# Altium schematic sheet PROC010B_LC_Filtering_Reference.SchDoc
size 431 x 279 mm; Date: Not shown in title block; ApprovedBy: Not shown in title block; CheckedBy: Not shown in title block; Author: Not shown in title block; CompanyName: Not shown in title block; DrawnBy: Adrian Ozer; Engineer: Not shown in title block; Organization: Not shown in title block; Address1: Not shown in title block; Address2: Not shown in title block; Address3: Not shown in title block; Address4: Not shown in title block; DocumentNumber: 5; Revision: Use project parameter SCH_Rev; SheetNumber: 5; SheetTotal: 16; PageSetup: Record=PageOptions¦CenterHorizontal=True¦CenterVertical=True¦PrintScale=1.00¦XCorrection=1.00¦YCorrection=1.00¦PrintKind=0¦BorderSize=5000000¦LeftOffset=0¦BottomOffset=0¦Orientation=2¦PaperLength=1000¦PaperWidth=1000¦Scale=100¦PaperSource=15¦PrintQuality=600¦MediaType=1¦DitherType=10¦PaperKind=Letter¦PrintScaleMode=1
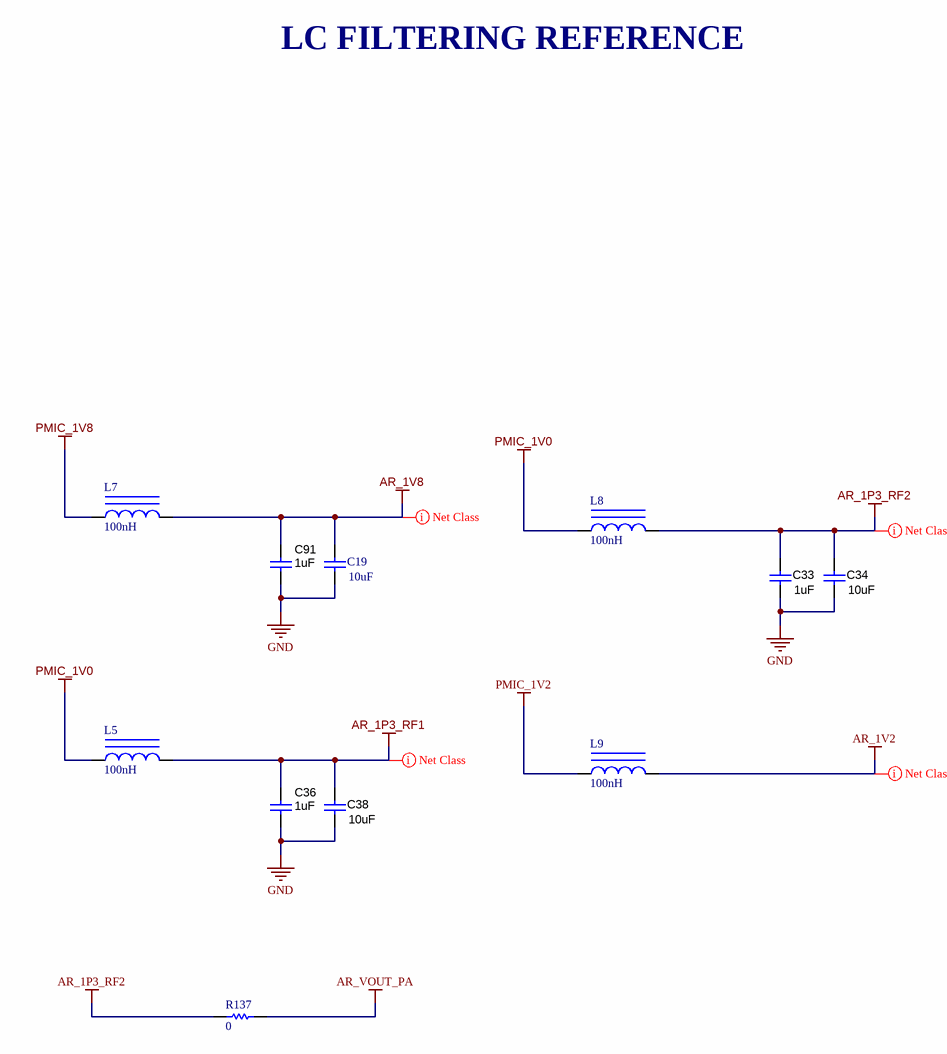
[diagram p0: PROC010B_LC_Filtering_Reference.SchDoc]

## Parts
C19  ValueDisplayed: 10uF  [0805_HV]  (hidden comment: GCM21BR71A106KE22L)
C33  ValueDisplayed: 1uF  [0603]  (hidden comment: GCM188R71C105KA64D)
C34  ValueDisplayed: 10uF  [0805_HV]  (hidden comment: GCM21BR71A106KE22L)
C36  ValueDisplayed: 1uF  [0603]  (hidden comment: GCM188R71C105KA64D)
C38  ValueDisplayed: 10uF  [0805_HV]  (hidden comment: GCM21BR71A106KE22L)
C91  ValueDisplayed: 1uF  [0603]  (hidden comment: GCM188R71C105KA64D)
L5  ValueDisplayed: 100nH  [NLCV32]  (hidden comment: NLCV32T-R10M-EFRD)
L7  ValueDisplayed: 100nH  [NLCV32]  (hidden comment: NLCV32T-R10M-EFRD)
L8  ValueDisplayed: 100nH  [NLCV32]  (hidden comment: NLCV32T-R10M-EFRD)
L9  ValueDisplayed: 100nH  [NLCV32]  (hidden comment: NLCV32T-R10M-EFRD)
R137  ValueDisplayed: 0  [0603]  (hidden comment: MCT06030Z0000ZP500)

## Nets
AR_1P3_RF1: C36.2 C38.2 L5.2
AR_1P3_RF2: C33.2 C34.2 L8.2 R137.1
AR_1V2: L9.2
AR_1V8: C19.1 C91.2 L7.2
AR_VOUT_PA: R137.2
GND: C19.2 C33.1 C34.1 C36.1 C38.1 C91.1
PMIC_1V0: L5.1 L8.1
PMIC_1V2: L9.1
PMIC_1V8: L7.1

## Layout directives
net class PWR: AR_1P3_RF1, AR_1P3_RF2, AR_1V2, AR_1V8

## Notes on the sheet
- LC FILTERING REFERENCE

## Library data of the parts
C19 = CMP-0008017-2: CAP, CERM, 10 uF, 10 V, +/- 10%, X7R, 0805; Manufacturer: MuRata; TaMin_C: -55°C; Polarized: N; SizeAreaWB_mm2: 6.75; Value1: Unknown; U/M: EA; Value: 10uF; TaMax_C: 125°C; SizeZ_mm: 1.45; SizeX_mm: 2; SizeY_mm: 1.25; Cap_Case: 0805; Value2: 10V; SizeArea_mm2: 2.5; Cap_F: 10µF; AEC Category: Q200
C33 C36 C91 = CMP-0007136-5: CAP, CERM, 1 uF, 16 V, +/- 10%, X7R, AEC-Q200 Grade 1, 0603; Manufacturer: MuRata; TaMin_C: -55°C; Polarized: N; SizeAreaWB_mm2: 4.68; Value1: Unknown; U/M: EA; Value: 1uF; TaMax_C: 125°C; SizeZ_mm: 1; SizeX_mm: 1.6; SizeY_mm: 0.8; Value2: 16V; SizeArea_mm2: 1.28; AEC Qualified: Y; Cap_F: 1µF; AEC Category: Q200
C34 C38 = CMP-0008017-2: CAP, CERM, 10 uF, 10 V, +/- 10%, X7R, 0805; Manufacturer: MuRata; TaMin_C: -55°C; Polarized: N; SizeAreaWB_mm2: 6.75; Value1: Unknown; U/M: EA; Value: 10uF; TaMax_C: 125°C; SizeZ_mm: 1.45; SizeX_mm: 2; SizeY_mm: 1.25; Cap_Case: 0805; Value2: 10V; SizeArea_mm2: 2.5; CompType: Capacitor; Cap_F: 10µF; AEC Category: Q200
L5 L7-L9 = CMP-0083745-1: Inductor, Wirewound, Ferrite, 100 nH, 2.85 A, 0.024 ohm, AEC-Q200 Grade 1, SMD; Manufacturer: TDK; Isat: 2.85A @ 10% inductance drop; Irms: 2.85A @ 40C rise; SizeAreaWB_mm2: 13.44; DCR_ohm: 0.024; Value: 100nH; Imax_A: 2.85A; SizeZ_mm: 2.5; SizeX_mm: 3.2; SizeY_mm: 2.2; SizeArea_mm2: 7.04; AEC Qualified: Y; AEC Grade: 1; AEC Category: Q200
R137 = CMP-0025884-3: RES, 0, 5%, 0.125 W, 0603; Manufacturer: Vishay/Beyschlag; Power_W: 125mW; TempCo: ppm/C; Value_Code: 0000; U/M: EA; Value: 0; EIA_Code: E24; SizeX_mm: 1.6; SizeY_mm: 0.8; SizeZ_mm: 1; Value2: 0.125W; SizeArea_mm2: 1.28; CompType: Resistor; AEC Qualified: N; AEC Category: Q200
